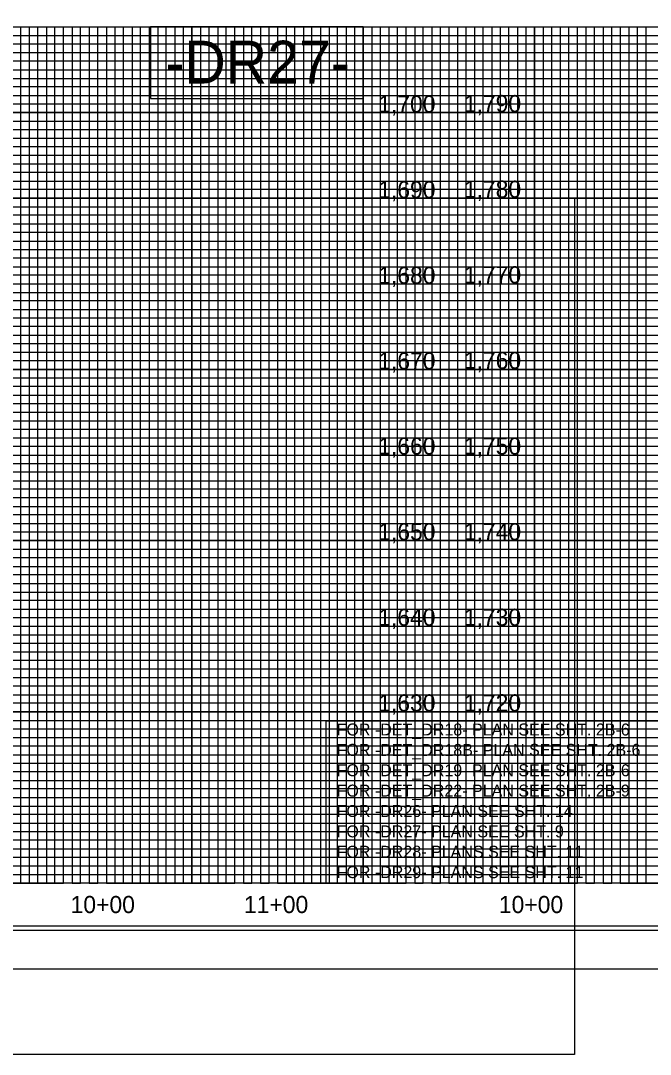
# Model space of a CAD drawing. Extents: x 505692 to 527456, y 415959 to 439886.
# Drawn here: x 506759 to 507126, y 438711 to 439315 of the extents above; entities that cross this region are included whole.
import ezdxf

# ---------------------------------------------------------------- set-up
doc = ezdxf.new("R2010")
doc.units = 0
for name, color, linetype in [('Exist Vertical Profile Vertical Axis Label', 7, 'Continuous'), ('Old_Level_1', 7, 'Continuous'), ('Prop Grid Mask', 7, 'Continuous'), ('Scratch_Level_4', 7, 'Continuous'), ('Sheet Cutting Line CELL', 7, 'Continuous'), ('Sheet Data Field CELL', 7, 'Continuous'), ('Sheet DOT Grid CELL', 7, 'Continuous'), ('Sheet Layout Profile Border Port 2', 7, 'Continuous'), ('Sheet Plot Border Inside CELL', 7, 'Continuous'), ('Sheet Plot Border Outside CELL', 7, 'Continuous'), ('Sheet Profile CELL', 7, 'Continuous'), ('Sheet Profile Grid Major CELL', 7, 'Continuous'), ('Sheet Profile Grid Middle CELL', 7, 'Continuous'), ('Sheet Profile Grid Minor CELL', 7, 'Continuous')]:
    doc.layers.add(name, color=color, linetype=linetype)

msp = doc.modelspace()

# ---------------------------------------------------------------- linework, layer by layer
at = {"layer": 'Prop Grid Mask'}
for points in [[(506958.68, 439311.14), (506834.38, 439311.14), (506834.38, 439269.44), (506958.68, 439269.44)], [(506936.92, 438906), (507141.48, 438906), (507141.48, 438811.14), (506936.92, 438811.14)]]:
    msp.add_lwpolyline(points, close=True, dxfattribs=at)
at = {"layer": 'Scratch_Level_4'}
for points in [[(506758.68, 439311.14), (507008.68, 439311.14), (507008.68, 438811.14), (506758.68, 438811.14)], [(507058.68, 439261.14), (507308.68, 439261.14), (507308.68, 438811.14), (507058.68, 438811.14)]]:
    msp.add_lwpolyline(points, close=True, dxfattribs=at)
at = {"layer": 'Sheet Cutting Line CELL'}
msp.add_line((505691.68, 438761.14), (507375.68, 438761.14), dxfattribs=at)
at = {"layer": 'Sheet DOT Grid CELL'}
for p, q in [((505858.68, 439311.14), (507358.56, 439311.14)), ((506808.68, 439311.14), (506808.68, 438811.14)), ((506858.68, 439311.14), (506858.68, 438811.14)), ((506908.68, 439311.14), (506908.68, 438811.14)), ((506958.68, 439311.14), (506958.68, 438811.14)), ((507008.68, 439311.14), (507008.68, 438811.14)), ((507058.68, 439311.14), (507058.68, 438811.14)), ((507108.68, 439311.14), (507108.68, 438811.14)), ((505858.68, 439261.14), (507358.56, 439261.14)), ((505858.68, 439211.14), (507358.56, 439211.14)), ((505858.68, 439161.14), (507358.56, 439161.14)), ((505858.68, 439111.14), (507358.56, 439111.14)), ((505858.68, 439061.14), (507358.56, 439061.14)), ((505858.68, 439011.14), (507358.56, 439011.14)), ((505858.68, 438961.14), (507358.56, 438961.14)), ((505858.68, 438911.14), (507358.56, 438911.14)), ((505858.68, 438861.14), (507358.56, 438861.14))]:
    msp.add_line(p, q, dxfattribs=at)
at = {"layer": 'Sheet Layout Profile Border Port 2'}
msp.add_lwpolyline([(506731.9, 439211.14), (507081.9, 439211.14), (507081.9, 438711.14), (506731.9, 438711.14)], close=True, dxfattribs=at)
at = {"layer": 'Sheet Plot Border Inside CELL'}
msp.add_lwpolyline([(505704.68, 438783.59), (507371.18, 438783.59), (507371.18, 439838.69), (505704.68, 439838.69)], close=True, dxfattribs=at)
at = {"layer": 'Sheet Plot Border Outside CELL'}
msp.add_lwpolyline([(505691.68, 438761.14), (507375.68, 438761.14), (507375.68, 439861.14), (505691.68, 439861.14)], close=True, dxfattribs=at)
at = {"layer": 'Sheet Profile CELL'}
for p, q in [((505858.68, 439311.14), (507358.68, 439311.14)), ((507008.68, 439311.14), (507008.68, 438906)), ((507358.68, 438811.14), (505858.68, 438811.14)), ((505858.68, 438786.14), (507358.68, 438786.14))]:
    msp.add_line(p, q, dxfattribs=at)
msp.add_lwpolyline([(507358.68, 439836.14), (505858.68, 439836.14), (505858.68, 438786.14), (507358.68, 438786.14)], close=True, dxfattribs=at)
at = {"layer": 'Sheet Profile Grid Major CELL'}
for p, q in [((506858.68, 439311.14), (506908.68, 439311.14)), ((506858.68, 439311.14), (506908.68, 439311.14)), ((506958.68, 439311.14), (507008.68, 439311.14)), ((506958.68, 439311.14), (507008.68, 439311.14)), ((507058.68, 439311.14), (507108.68, 439311.14)), ((507058.68, 439311.14), (507108.68, 439311.14)), ((507056.02, 438811.14), (507056.02, 438811.14))]:
    msp.add_line(p, q, dxfattribs=at)
for points in [[(506758.68, 439311.14), (506808.68, 439311.14), (506808.68, 438811.14), (506858.68, 438811.14), (506858.68, 439311.14), (506908.68, 439311.14), (506908.68, 438811.14), (506958.68, 438811.14), (506958.68, 439311.14), (507008.68, 439311.14), (507008.68, 438811.14), (507058.68, 438811.14), (507058.68, 439311.14), (507108.68, 439311.14), (507108.68, 438811.14), (507158.68, 438811.14), (507158.68, 439311.14), (507208.68, 439311.14), (507208.68, 438811.14), (507258.68, 438811.14), (507258.68, 438811.14), (507258.68, 439311.14), (507308.68, 439311.14), (507308.68, 438811.14)], [(507358.68, 439261.14), (505858.68, 439261.14)], [(507358.68, 439211.14), (505858.68, 439211.14), (505858.68, 439161.14), (507358.68, 439161.14)], [(507358.68, 439111.14), (505858.68, 439111.14), (505858.68, 439061.14), (507358.68, 439061.14)], [(507358.68, 439011.14), (505858.68, 439011.14), (505858.68, 438961.14), (507358.68, 438961.14)], [(507358.68, 438911.14), (505858.68, 438911.14), (505858.68, 438911.14), (505858.68, 438861.14), (507358.68, 438861.14)], [(507358.68, 438811.14), (505858.68, 438811.14)]]:
    msp.add_lwpolyline(points, dxfattribs=at)
at = {"layer": 'Sheet Profile Grid Middle CELL'}
for points in [[(506733.68, 438811.14), (506783.68, 438811.14), (506783.68, 439311.14), (506833.68, 439311.14), (506833.68, 438811.14), (506883.68, 438811.14), (506883.68, 439311.14), (506933.68, 439311.14), (506933.68, 438811.14), (506983.68, 438811.14), (506983.68, 439311.14), (507033.68, 439311.14), (507033.68, 438811.14), (507083.68, 438811.14), (507083.68, 439311.14), (507133.68, 439311.14), (507133.68, 438811.14), (507183.68, 438811.14), (507183.68, 439311.14), (507233.68, 439311.14), (507233.68, 438811.14), (507283.68, 438811.14), (507283.68, 439311.14)], [(505858.68, 439286.14), (507358.68, 439286.14)], [(507358.68, 439236.14), (505858.68, 439236.14), (505858.68, 439186.14), (507358.68, 439186.14)], [(507358.68, 439136.14), (505858.68, 439136.14), (505858.68, 439086.14), (507358.68, 439086.14)], [(507358.68, 439036.14), (505858.68, 439036.14), (505858.68, 438986.14), (507358.68, 438986.14)], [(507358.68, 438936.14), (505858.68, 438936.14), (505858.68, 438886.14), (507358.68, 438886.14)], [(507358.68, 438836.14), (505858.68, 438836.14)]]:
    msp.add_lwpolyline(points, dxfattribs=at)
at = {"layer": 'Sheet Profile Grid Minor CELL'}
for p, q in [((505908.68, 439306.14), (507308.68, 439306.14)), ((507308.68, 439301.14), (505908.68, 439301.14)), ((505908.68, 439296.14), (507308.68, 439296.14)), ((507308.68, 439291.14), (505908.68, 439291.14)), ((505908.68, 439281.14), (507308.68, 439281.14)), ((507308.68, 439276.14), (505908.68, 439276.14)), ((505908.68, 439271.14), (507308.68, 439271.14)), ((507308.68, 439266.14), (505908.68, 439266.14)), ((505908.68, 439256.14), (507308.68, 439256.14)), ((507308.68, 439251.14), (505908.68, 439251.14)), ((505908.68, 439246.14), (507308.68, 439246.14)), ((507308.68, 439241.14), (505908.68, 439241.14)), ((505908.68, 439231.14), (507308.68, 439231.14)), ((507308.68, 439226.14), (505908.68, 439226.14)), ((505908.68, 439221.14), (507308.68, 439221.14)), ((507308.68, 439216.14), (505908.68, 439216.14)), ((505908.68, 439206.14), (507308.68, 439206.14)), ((507308.68, 439201.14), (505908.68, 439201.14)), ((505908.68, 439196.14), (507308.68, 439196.14)), ((507308.68, 439191.14), (505908.68, 439191.14)), ((505908.68, 439181.14), (507308.68, 439181.14)), ((507308.68, 439176.14), (505908.68, 439176.14)), ((505908.68, 439171.14), (507308.68, 439171.14)), ((507308.68, 439166.14), (505908.68, 439166.14)), ((505908.68, 439156.14), (507308.68, 439156.14)), ((507308.68, 439151.14), (505908.68, 439151.14)), ((505908.68, 439146.14), (507308.68, 439146.14)), ((507308.68, 439141.14), (505908.68, 439141.14)), ((505908.68, 439131.14), (507308.68, 439131.14)), ((507308.68, 439126.14), (505908.68, 439126.14)), ((505908.68, 439121.14), (507308.68, 439121.14)), ((507308.68, 439116.14), (505908.68, 439116.29)), ((505908.68, 439106.14), (507308.68, 439106.14)), ((507308.68, 439101.14), (505908.68, 439101.14)), ((505908.68, 439096.14), (507308.68, 439096.14)), ((507308.68, 439091.14), (505908.68, 439091.14)), ((505908.68, 439081.14), (507308.68, 439081.14)), ((507308.68, 439076.14), (505908.68, 439076.14)), ((505908.68, 439071.14), (507308.68, 439071.14)), ((507308.68, 439066.14), (505908.68, 439066.14)), ((505908.68, 439056.14), (507308.68, 439056.14)), ((507308.68, 439051.14), (505908.68, 439051.14)), ((505908.68, 439046.14), (507308.68, 439046.14)), ((507308.68, 439041.14), (505908.68, 439041.14)), ((505908.68, 439031.14), (507308.68, 439031.14)), ((507308.68, 439026.14), (505908.68, 439026.14)), ((505908.68, 439021.14), (507308.68, 439021.14)), ((507308.68, 439016.14), (505908.68, 439016.14)), ((505908.68, 439006.14), (507308.68, 439006.14)), ((507308.68, 439001.14), (505908.68, 439001.14)), ((505908.68, 438996.14), (507308.68, 438996.14)), ((507308.68, 438991.14), (505908.68, 438991.14)), ((505908.68, 438981.14), (507308.68, 438981.14)), ((507308.68, 438976.14), (505908.68, 438976.14)), ((505908.68, 438971.14), (507308.68, 438971.14)), ((507308.68, 438966.14), (505908.68, 438966.14)), ((505908.68, 438956.14), (507308.68, 438956.14)), ((507308.68, 438951.14), (505908.68, 438951.14)), ((505908.68, 438946.14), (507308.68, 438946.14)), ((507308.68, 438941.14), (505908.68, 438941.14)), ((505908.68, 438931.14), (507308.68, 438931.14)), ((507308.68, 438926.14), (505908.68, 438926.14)), ((505908.68, 438921.14), (507308.68, 438921.14)), ((507308.68, 438916.14), (505908.68, 438916.14)), ((505908.68, 438906.14), (507308.68, 438906.14)), ((507308.68, 438901.14), (505908.68, 438901.14)), ((505908.68, 438896.14), (507308.68, 438896.14)), ((507308.68, 438891.14), (505908.68, 438891.14)), ((505908.68, 438881.14), (507308.68, 438881.14)), ((507308.68, 438876.14), (505908.68, 438876.14)), ((505908.68, 438871.14), (507308.68, 438871.14)), ((507308.68, 438866.14), (505908.68, 438866.14)), ((505908.68, 438856.14), (507308.68, 438856.14)), ((507308.68, 438851.14), (505908.68, 438851.14)), ((505908.68, 438846.14), (507308.68, 438846.14)), ((507308.68, 438841.14), (505908.68, 438841.14)), ((505908.68, 438831.14), (507308.68, 438831.14)), ((507308.68, 438826.14), (505908.68, 438826.14)), ((505908.68, 438821.14), (507308.68, 438821.14)), ((505908.68, 438816.14), (507308.68, 438816.14))]:
    msp.add_line(p, q, dxfattribs=at)
for points in [[(506753.68, 439311.14), (506763.68, 439311.14), (506763.68, 438811.14), (506768.68, 438811.14), (506768.68, 439311.14), (506773.68, 439311.14), (506773.68, 438811.14), (506778.68, 438811.14), (506778.68, 439311.14), (506788.68, 439311.14), (506788.68, 438811.14), (506793.68, 438811.14), (506793.68, 439311.14), (506798.68, 439311.14), (506798.68, 438811.14), (506803.68, 438811.14), (506803.68, 439311.14), (506813.68, 439311.14), (506813.68, 438811.14), (506818.68, 438811.14), (506818.68, 439311.14), (506823.68, 439311.14), (506823.68, 438811.14), (506828.68, 438811.14), (506828.68, 439311.14), (506838.68, 439311.14), (506838.68, 438811.14), (506843.68, 438811.14), (506843.68, 439311.14), (506848.68, 439311.14), (506848.68, 438811.14), (506853.68, 438811.14), (506853.68, 439311.14), (506863.68, 439311.14), (506863.68, 438811.14), (506868.68, 438811.14), (506868.68, 439311.14), (506873.68, 439311.14), (506873.68, 438811.14), (506878.68, 438811.14), (506878.68, 439311.14), (506888.68, 439311.14), (506888.68, 438811.14), (506893.68, 438811.14), (506893.68, 439311.14), (506898.68, 439311.14), (506898.68, 438811.14), (506903.68, 438811.14), (506903.68, 439311.14), (506913.68, 439311.14), (506913.68, 438811.14), (506918.68, 438811.14), (506918.68, 439311.14), (506923.68, 439311.14), (506923.68, 438811.14), (506928.68, 438811.14), (506928.68, 439311.14), (506938.68, 439311.14), (506938.68, 438811.14), (506943.68, 438811.14), (506943.68, 439311.14), (506948.68, 439311.14), (506948.68, 438811.14), (506953.68, 438811.14), (506953.68, 439311.14), (506963.68, 439311.14), (506963.68, 438811.14), (506968.68, 438811.14), (506968.68, 439311.14), (506973.68, 439311.14), (506973.68, 438811.14), (506978.68, 438811.14), (506978.68, 439311.14), (506988.68, 439311.14), (506988.68, 438811.14), (506993.68, 438811.14), (506993.68, 439311.14), (506998.68, 439311.14), (506998.68, 438811.14), (507003.68, 438811.14), (507003.68, 439311.14), (507013.68, 439311.14), (507013.68, 438811.14), (507018.68, 438811.14), (507018.68, 439311.14), (507023.68, 439311.14), (507023.68, 438811.14), (507028.68, 438811.14), (507028.68, 439311.14), (507038.68, 439311.14), (507038.68, 438811.14), (507043.68, 438811.14), (507043.68, 439311.14), (507048.68, 439311.14), (507048.68, 438811.14)], [(507048.68, 438811.14), (507053.68, 438811.14), (507053.68, 439311.14), (507063.68, 439311.14), (507063.68, 438811.14), (507068.68, 438811.14), (507068.68, 439311.14), (507073.68, 439311.14), (507073.68, 438811.14), (507078.68, 438811.14), (507078.68, 439311.14), (507088.68, 439311.14), (507088.68, 438811.14), (507093.68, 438811.14), (507093.68, 439311.14), (507098.68, 439311.14), (507098.68, 438811.14), (507103.68, 438811.14), (507103.68, 439311.14), (507113.68, 439311.14), (507113.68, 438811.14), (507118.68, 438811.14), (507118.68, 439311.14), (507123.68, 439311.14), (507123.68, 438811.14), (507128.68, 438811.14)]]:
    msp.add_lwpolyline(points, dxfattribs=at)

# ---------------------------------------------------------------- texts
at = {"layer": 'Exist Vertical Profile Vertical Axis Label'}
for s, p in [('1,700', (506967.37, 439261.14)), ('1,790', (507017.37, 439261.39)), ('1,690', (506967.37, 439211.14)), ('1,780', (507017.37, 439211.39)), ('1,680', (506967.37, 439161.14)), ('1,770', (507017.37, 439161.39)), ('1,670', (506967.37, 439111.14)), ('1,760', (507017.37, 439111.39)), ('1,660', (506967.37, 439061.39)), ('1,750', (507017.37, 439061.39)), ('1,650', (506967.37, 439011.39)), ('1,740', (507017.37, 439011.39)), ('1,640', (506967.37, 438961.39)), ('1,730', (507017.37, 438961.39)), ('1,630', (506967.37, 438911.39)), ('1,720', (507017.37, 438911.39)), ('10+00', (506787.81, 438793.64)), ('11+00', (506889, 438793.64)), ('10+00', (507037.81, 438793.64))]:
    msp.add_text(s, height=10, dxfattribs=at).set_placement(p)
at = {"layer": 'Old_Level_1'}
msp.add_text('-DR27-', height=25, dxfattribs=at).set_placement((506843.13, 439278.11))
at = {"layer": 'Sheet Data Field CELL'}
for s, p in [('FOR -DET_DR18- PLAN SEE SHT. 2B-6', (506943.1, 438897.35)), ('FOR -DET_DR18B- PLAN SEE SHT. 2B-6', (506943.1, 438885.45)), ('FOR -DET_DR19- PLAN SEE SHT. 2B-6', (506943.1, 438873.55)), ('FOR -DET_DR22- PLAN SEE SHT. 2B-9', (506943.1, 438861.65)), ('FOR -DR26- PLAN SEE SHT. 14', (506943.1, 438849.75)), ('FOR -DR27- PLAN SEE SHT. 9', (506943.1, 438837.85)), ('FOR -DR28- PLANS SEE SHT. 11', (506943.1, 438825.95)), ('FOR -DR29- PLANS SEE SHT. 11', (506943.1, 438814.05))]:
    msp.add_text(s, height=7, rotation=360, dxfattribs=at).set_placement(p)

doc.saveas('drawing.dxf')
